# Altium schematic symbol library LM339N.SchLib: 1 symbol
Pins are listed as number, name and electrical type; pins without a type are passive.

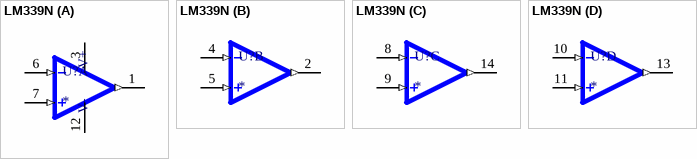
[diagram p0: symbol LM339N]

## LM339N
designator U?
Quad Voltage Comparators; MF: TAEJIN; MP: LM339N
footprint DIP764W47P254L1920H431Q14
part A pins: 1 OUT1 (out), 3 VCC (power), 6 IN1- (in), 7 IN1+ (in), 12 GND (power)
part B pins: 2 OUT2 (out), 4 IN2- (in), 5 IN2+ (in)
part C pins: 8 IN3- (in), 9 IN3+ (in), 14 OUT3 (out)
part D pins: 10 IN4- (in), 11 IN4+ (in), 13 OUT4 (out)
